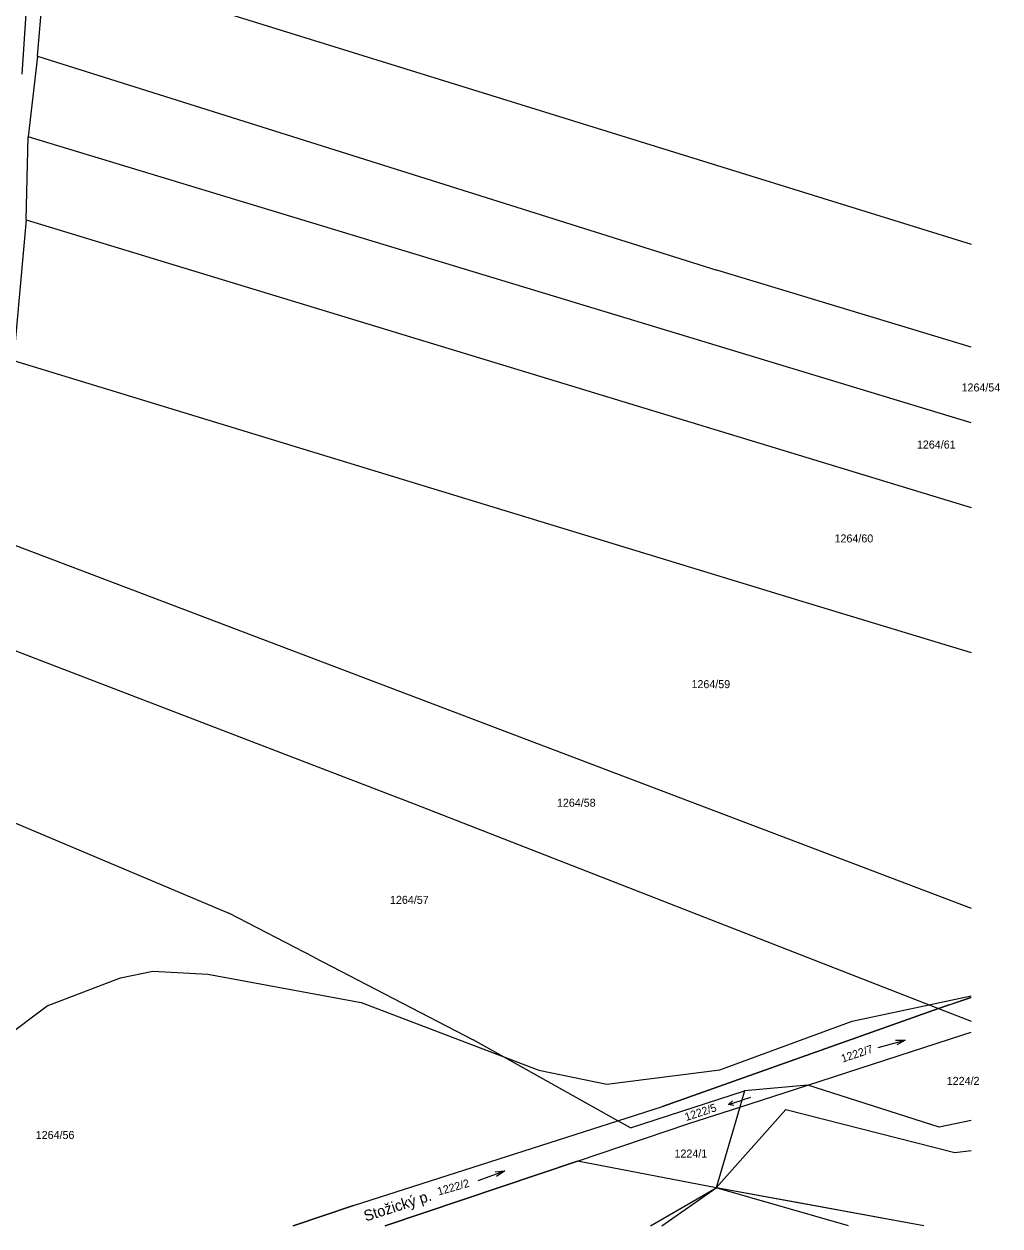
# Model space of a CAD drawing. Extents: x -779618 to -776429, y -1144546 to -1143350.
# Drawn here: x -776635.9 to -776428.6, y -1144546.2 to -1144290.9 of the extents above; entities that cross this region are included whole.
import ezdxf

# ---------------------------------------------------------------- set-up
doc = ezdxf.new("R2010")
doc.units = 0
for name, color, linetype in [('1', 7, 'Continuous'), ('11', 7, 'Continuous'), ('2', 7, 'Continuous'), ('3', 7, 'Continuous'), ('7', 7, 'Continuous')]:
    doc.layers.add(name, color=color, linetype=linetype)

msp = doc.modelspace()

# ---------------------------------------------------------------- linework, layer by layer
at = {"layer": '1'}
for p, q in [((-776633, -1144297.73), (-776631.25, -1144276.64)), ((-776631.25, -1144276.64), (-776434.77, -1144337.64)), ((-776636.28, -1144301.51), (-776635.38, -1144288.7)), ((-776633, -1144297.73), (-776635, -1144314.84)), ((-776633, -1144297.73), (-776488.73, -1144343.19)), ((-776635.44, -1144332.47), (-776635, -1144314.84)), ((-776434.77, -1144375.6), (-776635, -1144314.84)), ((-776635.44, -1144332.47), (-776638.11, -1144362.4)), ((-776635.44, -1144332.47), (-776434.77, -1144393.61)), ((-776434.77, -1144359.52), (-776488.73, -1144343.19)), ((-776638.11, -1144362.4), (-776471.4, -1144413.28)), ((-776641.45, -1144400.26), (-776434.77, -1144478.67)), ((-776471.4, -1144413.28), (-776434.77, -1144424.37)), ((-776643.31, -1144421.84), (-776553.05, -1144456.51)), ((-776648.85, -1144455.92), (-776592.37, -1144479.79)), ((-776553.05, -1144456.51), (-776441.71, -1144500.03)), ((-776574.33, -1144489.12), (-776592.37, -1144479.79)), ((-776574.33, -1144489.12), (-776540.5, -1144506.68)), ((-776439.44, -1144499.23), (-776434.77, -1144497.63)), ((-776441.71, -1144500.03), (-776500.26, -1144520.82)), ((-776439.44, -1144499.23), (-776441.71, -1144500.03)), ((-776441.71, -1144500.03), (-776434.77, -1144502.73)), ((-776469.45, -1144516.28), (-776436.48, -1144505.62)), ((-776436.48, -1144505.62), (-776434.77, -1144505.03)), ((-776509.78, -1144523.87), (-776540.5, -1144506.68)), ((-776507.1, -1144525.37), (-776482.87, -1144517.48)), ((-776483.88, -1144520.95), (-776469.45, -1144516.28)), ((-776482.87, -1144517.48), (-776483.88, -1144520.95)), ((-776469.45, -1144516.28), (-776482.87, -1144517.48)), ((-776441.51, -1144525.21), (-776469.45, -1144516.28)), ((-776509.78, -1144523.87), (-776500.26, -1144520.82)), ((-776494.72, -1144524.45), (-776483.88, -1144520.95)), ((-776483.88, -1144520.95), (-776488.9, -1144538.09)), ((-776488.9, -1144538.09), (-776474.1, -1144521.45)), ((-776474.1, -1144521.45), (-776438.23, -1144530.56)), ((-776565.92, -1144541.83), (-776509.78, -1144523.87)), ((-776518.33, -1144532.42), (-776494.72, -1144524.45)), ((-776507.1, -1144525.37), (-776509.78, -1144523.87)), ((-776434.77, -1144523.81), (-776441.51, -1144525.21)), ((-776438.23, -1144530.56), (-776434.77, -1144530.16)), ((-776559.16, -1144546.2), (-776518.33, -1144532.42)), ((-776488.9, -1144538.09), (-776518.33, -1144532.42)), ((-776502.82, -1144546.2), (-776488.9, -1144538.09)), ((-776500.44, -1144546.2), (-776488.9, -1144538.09)), ((-776460.76, -1144546.2), (-776488.9, -1144538.09)), ((-776444.78, -1144546.2), (-776488.9, -1144538.09)), ((-776565.92, -1144541.83), (-776578.7, -1144546.2))]:
    msp.add_line(p, q, dxfattribs=at)
at = {"layer": '11'}
for points in [[(-776682.61, -1144546.2), (-776649.28, -1144513.21), (-776630.96, -1144499.43), (-776615.4, -1144493.47), (-776608.51, -1144492.06), (-776596.85, -1144492.7), (-776564.3, -1144498.71), (-776526.55, -1144513.12), (-776512.1, -1144516.1), (-776488.13, -1144513.07), (-776459.99, -1144502.69), (-776434.77, -1144497.31)], [(-776578.7, -1144546.2), (-776565.92, -1144541.83), (-776509.78, -1144523.87), (-776500.26, -1144520.82), (-776441.71, -1144500.03), (-776439.44, -1144499.23), (-776434.77, -1144497.64)], [(-776444.78, -1144546.2), (-776472.12, -1144541.17), (-776488.9, -1144538.09), (-776518.33, -1144532.42), (-776559.16, -1144546.2)]]:
    msp.add_lwpolyline(points, dxfattribs=at)
at = {"layer": '3'}
for p, q in [((-776454.51, -1144508.32), (-776448.73, -1144506.7)), ((-776539.43, -1144536.54), (-776533.79, -1144534.52))]:
    msp.add_line(p, q, dxfattribs=at)
for points in [[(-776450.79, -1144506.76), (-776448.73, -1144506.7), (-776450.52, -1144507.72)], [(-776535.84, -1144534.72), (-776533.79, -1144534.52), (-776535.5, -1144535.66)]]:
    msp.add_lwpolyline(points, dxfattribs=at)
at = {"layer": '7'}
for p in [(-776486.24, -1144520.43), (-776481.62, -1144518.89)]:
    msp.add_line(p, (-776483.39, -1144519.48), dxfattribs=at)
msp.add_lwpolyline([(-776485.13, -1144520.59), (-776486.24, -1144520.43), (-776485.45, -1144519.64)], dxfattribs=at)

# ---------------------------------------------------------------- texts
at = {"layer": '2'}
for s, p in [('1264/54', (-776436.78, -1144368.94)), ('1264/61', (-776446.26, -1144381.07)), ('1264/60', (-776463.75, -1144401.01)), ('1264/59', (-776494.13, -1144431.96)), ('1264/58', (-776522.7, -1144457.15)), ('1264/57', (-776558.15, -1144477.78)), ('1224/2', (-776439.92, -1144516.23)), ('1264/56', (-776633.38, -1144527.72)), ('1224/1', (-776497.74, -1144531.66))]:
    msp.add_text(s, height=1.7, dxfattribs=at).set_placement(p)
for s, height, rotation, p in [('1222/7', 1.7, 18.5638, (-776462.02, -1144511.5)), ('1222/5', 0.1, 17.7044, (-776481.6, -1144518.88)), ('1222/2', 1.7, 15.9282, (-776547.82, -1144539.73))]:
    msp.add_text(s, height=height, rotation=rotation, dxfattribs=at).set_placement(p)
at = {"layer": '7'}
for s, height, rotation, p in [('1222/5', 1.7, 18.2774, (-776495.24, -1144523.93)), ('Stožický p.', 2.3, 17.819, (-776563.28, -1144545.27))]:
    msp.add_text(s, height=height, rotation=rotation, dxfattribs=at).set_placement(p)

doc.saveas('drawing.dxf')
